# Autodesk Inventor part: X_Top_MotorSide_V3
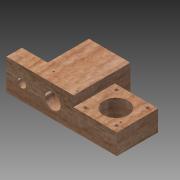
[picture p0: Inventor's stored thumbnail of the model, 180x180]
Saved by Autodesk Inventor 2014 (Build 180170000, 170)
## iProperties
Created: 2013-12
Part Number: X_Top_MotorSide_V3
Material: Birch
Document SubType Name: Modeling
Designer: Bram
Density: 0.512 g/cm^3
Appearance: Birch - Natural Medium Gloss
Author: Bram
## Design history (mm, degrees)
sketch "Sketch1"
  geometry: L1 (0, 0)-(107, 0); L2 (107, 0)-(107, 30); L3 (107, 30)-(42, 30); L4 (0, 20)-(0, 0); L5 (42, 30)-(42, 20); L6 (42, 20)-(0, 20); C1 r 7.5 at (62, 15); C2 r 4 at (92, 15)
  constraints: 12 end point, 2 centre point, 2 parallel, 1 horizontal, 1 perpendicular
  dimensions: "d6" = 15 diameter of C1; "d7" = 8 diameter of C2
extrude "Extrusion1" new body sketch "Sketch1" distance "d8" = 55; taper "d9" = 0 deg
sketch "Sketch2"
  geometry: L1 (0, 55)-(25, 55); L2 (25, 55)-(25, 15); L3 (25, 15)-(0, 15); L4 (0, 15)-(0, 55); 1 further point
  constraints: 8 end point, 2 parallel, 1 horizontal, 1 perpendicular
  dimensions: "d10" = 25 distance of L2.end L3.end; "d11" = 40 distance of L1.end L2.end
extrude "Extrusion2" cut sketch "Sketch2" distance "d12" = 55; taper "d13" = 0 deg
sketch "Sketch3"
  geometry: L1 (0, 55)-(42, 55); L2 (42, 55)-(42, 40); L3 (42, 40)-(0, 40); L4 (0, 40)-(0, 55); C1 r 12 at (21, 20); C2 r 1.5 at (6.224, 35.501); C3 r 1.5 at (36.5, 35.5); C4 r 1.5 at (36.224, 5.501); C5 r 1.5 at (6.224, 5.501)
  constraints: 8 end point, 5 centre point, 2 parallel, 1 horizontal, 1 perpendicular
  dimensions: "d14" = 42 distance of L2.end L3.end; "d15" = 15 distance of L1.end L2.end; "d16" = 24 diameter of C1; "d22" = 3 diameter of C2; "d23" = 3 diameter of C3; "d24" = 3 diameter of C4; "d25" = 3 diameter of C5
extrude "Extrusion3" cut sketch "Sketch3" distance "d26" = 55; taper "d27" = 0 deg
body "Solid1"
